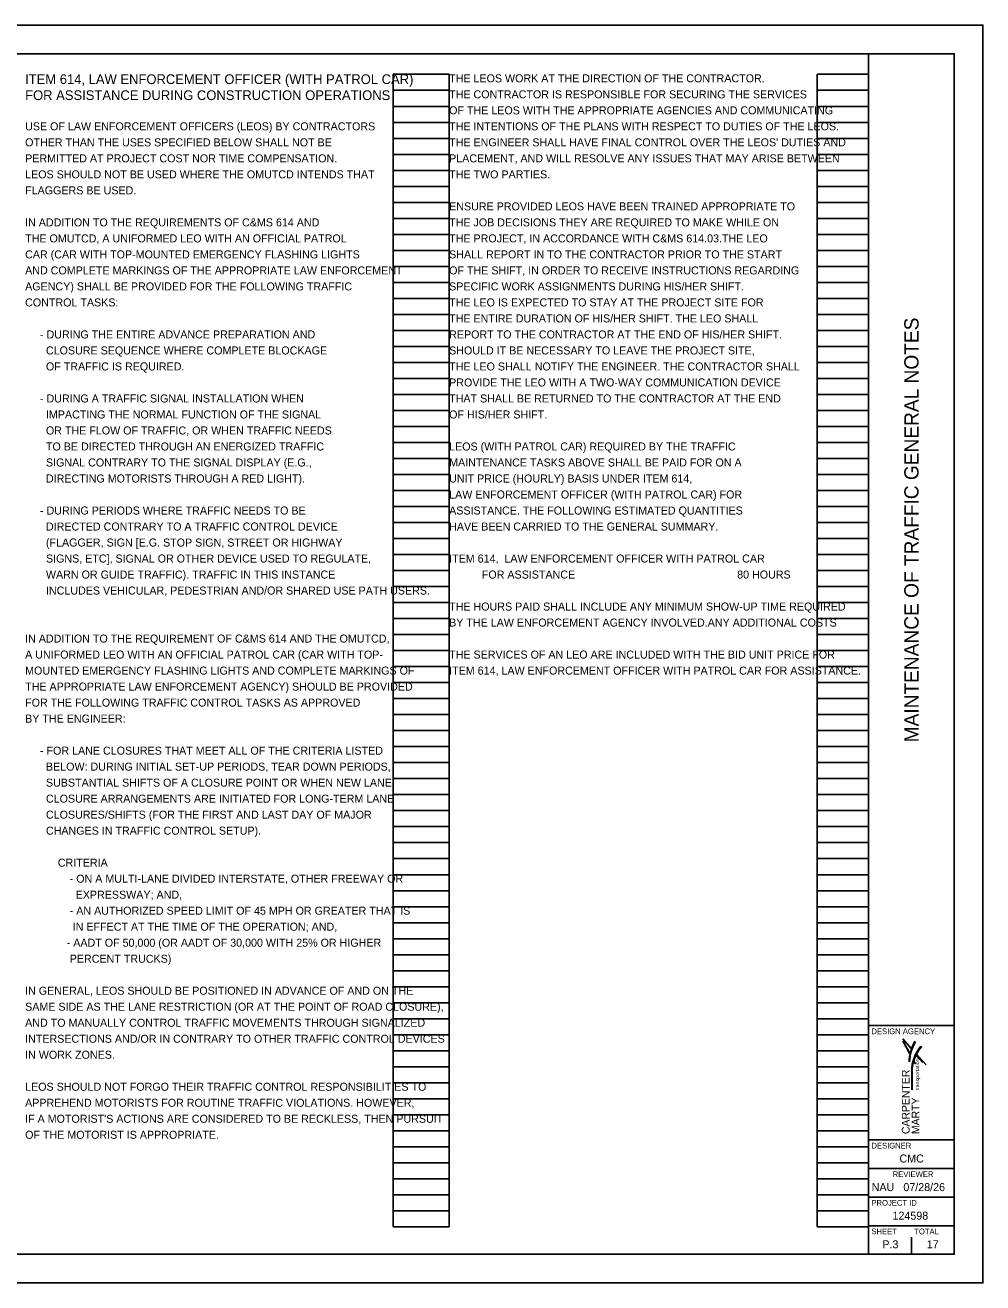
# Model space of a CAD drawing. Extents: x 0 to 34, y -31.6 to -9.6.
# Drawn here: x 17.24 to 34, y -31.62 to -9.62 of the extents above; entities that cross this region are included whole.
import ezdxf

# ---------------------------------------------------------------- set-up
doc = ezdxf.new("R2010")
doc.units = 0
for name, color, linetype in [('SH_Border', 7, 'Continuous'), ('SH_Cut_Line', 7, 'Continuous'), ('SH_Data', 7, 'Continuous'), ('SH_Text', 7, 'Continuous')]:
    doc.layers.add(name, color=color, linetype=linetype)

msp = doc.modelspace()

# ---------------------------------------------------------------- linework, layer by layer
at = {"layer": 'SH_Border'}
for p, q in [((32, -31.117), (32, -10.117)), ((32, -27.117), (33.5, -27.117)), ((32, -29.117), (33.5, -29.117)), ((32, -29.617), (33.5, -29.617)), ((32, -30.117), (33.5, -30.117)), ((32, -30.617), (33.5, -30.617))]:
    msp.add_line(p, q, dxfattribs=at)
msp.add_lwpolyline([(1.5, -10.117), (33.5, -10.117), (33.5, -31.117), (1.5, -31.117)], close=True, dxfattribs=at)
at = {"layer": 'SH_Cut_Line'}
msp.add_lwpolyline([(0, -31.617), (34, -31.617), (34, -9.617), (0, -9.617)], close=True, dxfattribs=at)
at = {"layer": 'SH_Data'}
for p, q in [((23.68, -30.637), (23.68, -10.477)), ((23.68, -10.477), (24.66, -10.477)), ((24.66, -30.637), (24.66, -10.477)), ((31.1, -30.637), (31.1, -10.477)), ((31.1, -10.477), (32, -10.477)), ((32, -30.637), (32, -10.477)), ((23.68, -10.757), (24.66, -10.757)), ((31.1, -10.757), (32, -10.757)), ((23.68, -11.037), (24.66, -11.037)), ((31.1, -11.037), (32, -11.037)), ((23.68, -11.317), (24.66, -11.317)), ((31.1, -11.317), (32, -11.317)), ((23.68, -11.597), (24.66, -11.597)), ((31.1, -11.597), (32, -11.597)), ((23.68, -11.877), (24.66, -11.877)), ((31.1, -11.877), (32, -11.877)), ((23.68, -12.157), (24.66, -12.157)), ((31.1, -12.157), (32, -12.157)), ((23.68, -12.437), (24.66, -12.437)), ((31.1, -12.437), (32, -12.437)), ((23.68, -12.717), (24.66, -12.717)), ((31.1, -12.717), (32, -12.717)), ((23.68, -12.997), (24.66, -12.997)), ((31.1, -12.997), (32, -12.997)), ((23.68, -13.277), (24.66, -13.277)), ((31.1, -13.277), (32, -13.277)), ((23.68, -13.557), (24.66, -13.557)), ((31.1, -13.557), (32, -13.557)), ((23.68, -13.837), (24.66, -13.837)), ((31.1, -13.837), (32, -13.837)), ((23.68, -14.117), (24.66, -14.117)), ((31.1, -14.117), (32, -14.117)), ((23.68, -14.397), (24.66, -14.397)), ((31.1, -14.397), (32, -14.397)), ((23.68, -14.677), (24.66, -14.677)), ((31.1, -14.677), (32, -14.677)), ((23.68, -14.957), (24.66, -14.957)), ((31.1, -14.957), (32, -14.957)), ((23.68, -15.237), (24.66, -15.237)), ((31.1, -15.237), (32, -15.237)), ((23.68, -15.517), (24.66, -15.517)), ((31.1, -15.517), (32, -15.517)), ((23.68, -15.797), (24.66, -15.797)), ((31.1, -15.797), (32, -15.797)), ((23.68, -16.077), (24.66, -16.077)), ((31.1, -16.077), (32, -16.077)), ((23.68, -16.357), (24.66, -16.357)), ((31.1, -16.357), (32, -16.357)), ((23.68, -16.637), (24.66, -16.637)), ((31.1, -16.637), (32, -16.637)), ((23.68, -16.917), (24.66, -16.917)), ((31.1, -16.917), (32, -16.917)), ((23.68, -17.197), (24.66, -17.197)), ((31.1, -17.197), (32, -17.197)), ((23.68, -17.477), (24.66, -17.477)), ((31.1, -17.477), (32, -17.477)), ((23.68, -17.757), (24.66, -17.757)), ((31.1, -17.757), (32, -17.757)), ((23.68, -18.037), (24.66, -18.037)), ((31.1, -18.037), (32, -18.037)), ((23.68, -18.317), (24.66, -18.317)), ((31.1, -18.317), (32, -18.317)), ((23.68, -18.597), (24.66, -18.597)), ((31.1, -18.597), (32, -18.597)), ((23.68, -18.877), (24.66, -18.877)), ((31.1, -18.877), (32, -18.877)), ((23.68, -19.157), (24.66, -19.157)), ((31.1, -19.157), (32, -19.157)), ((23.68, -19.437), (24.66, -19.437)), ((31.1, -19.437), (32, -19.437)), ((23.68, -19.717), (24.66, -19.717)), ((31.1, -19.717), (32, -19.717)), ((23.68, -19.997), (24.66, -19.997)), ((31.1, -19.997), (32, -19.997)), ((23.68, -20.277), (24.66, -20.277)), ((31.1, -20.277), (32, -20.277)), ((23.68, -20.557), (24.66, -20.557)), ((31.1, -20.557), (32, -20.557)), ((23.68, -20.837), (24.66, -20.837)), ((31.1, -20.837), (32, -20.837)), ((23.68, -21.117), (24.66, -21.117)), ((31.1, -21.117), (32, -21.117)), ((23.68, -21.397), (24.66, -21.397)), ((31.1, -21.397), (32, -21.397)), ((23.68, -21.677), (24.66, -21.677)), ((31.1, -21.677), (32, -21.677)), ((23.68, -21.957), (24.66, -21.957)), ((31.1, -21.957), (32, -21.957)), ((23.68, -22.237), (24.66, -22.237)), ((31.1, -22.237), (32, -22.237)), ((23.68, -22.517), (24.66, -22.517)), ((31.1, -22.517), (32, -22.517)), ((23.68, -22.797), (24.66, -22.797)), ((31.1, -22.797), (32, -22.797)), ((23.68, -23.077), (24.66, -23.077)), ((31.1, -23.077), (32, -23.077)), ((23.68, -23.357), (24.66, -23.357)), ((31.1, -23.357), (32, -23.357)), ((23.68, -23.637), (24.66, -23.637)), ((31.1, -23.637), (32, -23.637)), ((23.68, -23.917), (24.66, -23.917)), ((31.1, -23.917), (32, -23.917)), ((23.68, -24.197), (24.66, -24.197)), ((31.1, -24.197), (32, -24.197)), ((23.68, -24.477), (24.66, -24.477)), ((31.1, -24.477), (32, -24.477)), ((23.68, -24.757), (24.66, -24.757)), ((31.1, -24.757), (32, -24.757)), ((23.68, -25.037), (24.66, -25.037)), ((31.1, -25.037), (32, -25.037)), ((23.68, -25.317), (24.66, -25.317)), ((31.1, -25.317), (32, -25.317)), ((23.68, -25.597), (24.66, -25.597)), ((31.1, -25.597), (32, -25.597)), ((23.68, -25.877), (24.66, -25.877)), ((31.1, -25.877), (32, -25.877)), ((23.68, -26.157), (24.66, -26.157)), ((31.1, -26.157), (32, -26.157)), ((23.68, -26.437), (24.66, -26.437)), ((31.1, -26.437), (32, -26.437)), ((23.68, -26.717), (24.66, -26.717)), ((31.1, -26.717), (32, -26.717)), ((23.68, -26.997), (24.66, -26.997)), ((31.1, -26.997), (32, -26.997)), ((23.68, -27.277), (24.66, -27.277)), ((31.1, -27.277), (32, -27.277)), ((23.68, -27.557), (24.66, -27.557)), ((31.1, -27.557), (32, -27.557)), ((23.68, -27.837), (24.66, -27.837)), ((31.1, -27.837), (32, -27.837)), ((23.68, -28.117), (24.66, -28.117)), ((31.1, -28.117), (32, -28.117)), ((32.75, -28.117), (32.75, -28.117)), ((23.68, -28.397), (24.66, -28.397)), ((31.1, -28.397), (32, -28.397)), ((23.68, -28.677), (24.66, -28.677)), ((31.1, -28.677), (32, -28.677)), ((23.68, -28.957), (24.66, -28.957)), ((31.1, -28.957), (32, -28.957)), ((23.68, -29.237), (24.66, -29.237)), ((31.1, -29.237), (32, -29.237)), ((23.68, -29.517), (24.66, -29.517)), ((31.1, -29.517), (32, -29.517)), ((23.68, -29.797), (24.66, -29.797)), ((31.1, -29.797), (32, -29.797)), ((23.68, -30.077), (24.66, -30.077)), ((31.1, -30.077), (32, -30.077)), ((23.68, -30.357), (24.66, -30.357)), ((31.1, -30.357), (32, -30.357)), ((23.68, -30.637), (24.66, -30.637)), ((31.1, -30.637), (32, -30.637)), ((32.375, -30.942), (32.375, -30.942)), ((32.75, -31.117), (32.75, -30.817))]:
    msp.add_line(p, q, dxfattribs=at)
at = {"layer": 'SH_Text'}
for p, q in [((32.721, -27.6), (32.602, -27.385)), ((32.952, -27.764), (32.834, -27.626)), ((32.839, -27.615), (33.006, -27.801)), ((32.755, -28.239), (32.755, -27.913)), ((32.762, -28.239), (32.762, -27.913)), ((32.811, -27.776), (32.79, -27.737)), ((32.82, -27.783), (32.791, -27.731))]:
    msp.add_line(p, q, dxfattribs=at)
for points in [[(32.746, -27.513), (32.601, -27.351)], [(32.601, -27.351), (32.744, -27.519)], [(32.721, -27.6), (32.602, -27.385)], [(32.602, -27.385), (32.719, -27.606)]]:
    msp.add_lwpolyline(points, dxfattribs=at)
for centre, radius, start, end in [((33.432, -27.757), 0.721, 149.5704, 179.5529), ((33.373, -27.755), 0.654, 147.1423, 179.6525), ((33.426, -27.913), 0.671, 139.2898, 180.0106), ((33.433, -27.929), 0.672, 138.5126, 178.6075)]:
    msp.add_arc(centre, radius, start, end, dxfattribs=at)

# ---------------------------------------------------------------- texts
at = {"layer": 'SH_Data'}
msp.add_text('MAINTENANCE OF TRAFFIC GENERAL NOTES', height=0.25, rotation=90, dxfattribs=at).set_placement((32.875, -22.162))
for s, height, p in [('DESIGN AGENCY', 0.1, (32.05, -27.267)), ('DESIGNER', 0.1, (32.05, -29.267)), ('CMC', 0.14, (32.541, -29.512)), ('REVIEWER', 0.1, (32.422, -29.767)), ('NAU', 0.14, (32.055, -30.012)), ('07/28/26', 0.14, (32.609, -30.012)), ('PROJECT ID', 0.1, (32.05, -30.267)), ('124598', 0.14, (32.419, -30.512)), ('SHEET', 0.1, (32.05, -30.767)), ('TOTAL', 0.1, (32.8, -30.767)), ('P.3', 0.14, (32.241, -31.012)), ('17', 0.14, (33.018, -31.012))]:
    msp.add_text(s, height=height, dxfattribs=at).set_placement(p)
at = {"layer": 'SH_Text'}
for s, height, p in [('ITEM 614, LAW ENFORCEMENT OFFICER (WITH PATROL CAR)', 0.17, (17.24, -10.647)), ('THE LEOS WORK AT THE DIRECTION OF THE CONTRACTOR.', 0.14, (24.66, -10.617)), ('FOR ASSISTANCE DURING CONSTRUCTION OPERATIONS', 0.17, (17.24, -10.927)), ('THE CONTRACTOR IS RESPONSIBLE FOR SECURING THE SERVICES', 0.14, (24.66, -10.897)), ('OF THE LEOS WITH THE APPROPRIATE AGENCIES AND COMMUNICATING', 0.14, (24.66, -11.177)), ('USE OF LAW ENFORCEMENT OFFICERS (LEOS) BY CONTRACTORS', 0.14, (17.24, -11.457)), ('THE INTENTIONS OF THE PLANS WITH RESPECT TO DUTIES OF THE LEOS.', 0.14, (24.66, -11.457)), ('OTHER THAN THE USES SPECIFIED BELOW SHALL NOT BE', 0.14, (17.24, -11.737)), ("THE ENGINEER SHALL HAVE FINAL CONTROL OVER THE LEOS' DUTIES AND", 0.14, (24.66, -11.737)), ('PERMITTED AT PROJECT COST NOR TIME COMPENSATION.', 0.14, (17.24, -12.017)), ('PLACEMENT, AND WILL RESOLVE ANY ISSUES THAT MAY ARISE BETWEEN', 0.14, (24.66, -12.017)), ('LEOS SHOULD NOT BE USED WHERE THE OMUTCD INTENDS THAT', 0.14, (17.24, -12.297)), ('THE TWO PARTIES.', 0.14, (24.66, -12.297)), ('FLAGGERS BE USED.', 0.14, (17.24, -12.577)), ('ENSURE PROVIDED LEOS HAVE BEEN TRAINED APPROPRIATE TO', 0.14, (24.66, -12.857)), ('IN ADDITION TO THE REQUIREMENTS OF C&MS 614 AND', 0.14, (17.24, -13.137)), ('THE JOB DECISIONS THEY ARE REQUIRED TO MAKE WHILE ON', 0.14, (24.66, -13.137)), ('THE OMUTCD, A UNIFORMED LEO WITH AN OFFICIAL PATROL', 0.14, (17.24, -13.417)), ('THE PROJECT, IN ACCORDANCE WITH C&MS 614.03.THE LEO', 0.14, (24.66, -13.417)), ('CAR (CAR WITH TOP-MOUNTED EMERGENCY FLASHING LIGHTS', 0.14, (17.24, -13.697)), ('SHALL REPORT IN TO THE CONTRACTOR PRIOR TO THE START', 0.14, (24.66, -13.697)), ('AND COMPLETE MARKINGS OF THE APPROPRIATE LAW ENFORCEMENT', 0.14, (17.24, -13.977)), ('OF THE SHIFT, IN ORDER TO RECEIVE INSTRUCTIONS REGARDING', 0.14, (24.66, -13.977)), ('AGENCY) SHALL BE PROVIDED FOR THE FOLLOWING TRAFFIC', 0.14, (17.24, -14.257)), ('SPECIFIC WORK ASSIGNMENTS DURING HIS/HER SHIFT.', 0.14, (24.66, -14.257)), ('CONTROL TASKS:', 0.14, (17.24, -14.537)), ('THE LEO IS EXPECTED TO STAY AT THE PROJECT SITE FOR', 0.14, (24.66, -14.537)), ('THE ENTIRE DURATION OF HIS/HER SHIFT. THE LEO SHALL', 0.14, (24.66, -14.817)), ('     - DURING THE ENTIRE ADVANCE PREPARATION AND', 0.14, (17.24, -15.097)), ('REPORT TO THE CONTRACTOR AT THE END OF HIS/HER SHIFT.', 0.14, (24.66, -15.097)), ('       CLOSURE SEQUENCE WHERE COMPLETE BLOCKAGE', 0.14, (17.24, -15.377)), ('SHOULD IT BE NECESSARY TO LEAVE THE PROJECT SITE,', 0.14, (24.66, -15.377)), ('       OF TRAFFIC IS REQUIRED.', 0.14, (17.24, -15.657)), ('THE LEO SHALL NOTIFY THE ENGINEER. THE CONTRACTOR SHALL', 0.14, (24.66, -15.657)), ('PROVIDE THE LEO WITH A TWO-WAY COMMUNICATION DEVICE', 0.14, (24.66, -15.937)), ('     - DURING A TRAFFIC SIGNAL INSTALLATION WHEN', 0.14, (17.24, -16.217)), ('THAT SHALL BE RETURNED TO THE CONTRACTOR AT THE END', 0.14, (24.66, -16.217)), ('       IMPACTING THE NORMAL FUNCTION OF THE SIGNAL', 0.14, (17.24, -16.497)), ('OF HIS/HER SHIFT.', 0.14, (24.66, -16.497)), ('       OR THE FLOW OF TRAFFIC, OR WHEN TRAFFIC NEEDS', 0.14, (17.24, -16.777)), ('       TO BE DIRECTED THROUGH AN ENERGIZED TRAFFIC', 0.14, (17.24, -17.057)), ('LEOS (WITH PATROL CAR) REQUIRED BY THE TRAFFIC', 0.14, (24.66, -17.057)), ('       SIGNAL CONTRARY TO THE SIGNAL DISPLAY (E.G.,', 0.14, (17.24, -17.337)), ('MAINTENANCE TASKS ABOVE SHALL BE PAID FOR ON A', 0.14, (24.66, -17.337)), ('       DIRECTING MOTORISTS THROUGH A RED LIGHT).', 0.14, (17.24, -17.617)), ('UNIT PRICE (HOURLY) BASIS UNDER ITEM 614,', 0.14, (24.66, -17.617)), ('LAW ENFORCEMENT OFFICER (WITH PATROL CAR) FOR', 0.14, (24.66, -17.897)), ('     - DURING PERIODS WHERE TRAFFIC NEEDS TO BE', 0.14, (17.24, -18.177)), ('ASSISTANCE. THE FOLLOWING ESTIMATED QUANTITIES', 0.14, (24.66, -18.177)), ('       DIRECTED CONTRARY TO A TRAFFIC CONTROL DEVICE', 0.14, (17.24, -18.457)), ('HAVE BEEN CARRIED TO THE GENERAL SUMMARY.', 0.14, (24.66, -18.457)), ('       (FLAGGER, SIGN [E.G. STOP SIGN, STREET OR HIGHWAY', 0.14, (17.24, -18.737)), ('       SIGNS, ETC], SIGNAL OR OTHER DEVICE USED TO REGULATE,', 0.14, (17.24, -19.017)), ('ITEM 614,  LAW ENFORCEMENT OFFICER WITH PATROL CAR', 0.14, (24.66, -19.017)), ('       WARN OR GUIDE TRAFFIC). TRAFFIC IN THIS INSTANCE', 0.14, (17.24, -19.297)), ('           FOR ASSISTANCE ', 0.14, (24.66, -19.297)), ('80 HOURS', 0.14, (29.7, -19.297)), ('       INCLUDES VEHICULAR, PEDESTRIAN AND/OR SHARED USE PATH USERS.', 0.14, (17.24, -19.577)), ('THE HOURS PAID SHALL INCLUDE ANY MINIMUM SHOW-UP TIME REQUIRED', 0.14, (24.66, -19.857)), ('BY THE LAW ENFORCEMENT AGENCY INVOLVED.ANY ADDITIONAL COSTS', 0.14, (24.66, -20.137)), ('IN ADDITION TO THE REQUIREMENT OF C&MS 614 AND THE OMUTCD,', 0.14, (17.24, -20.417)), ('A UNIFORMED LEO WITH AN OFFICIAL PATROL CAR (CAR WITH TOP-', 0.14, (17.24, -20.697)), ('THE SERVICES OF AN LEO ARE INCLUDED WITH THE BID UNIT PRICE FOR', 0.14, (24.66, -20.697)), ('MOUNTED EMERGENCY FLASHING LIGHTS AND COMPLETE MARKINGS OF', 0.14, (17.24, -20.977)), ('ITEM 614, LAW ENFORCEMENT OFFICER WITH PATROL CAR FOR ASSISTANCE.', 0.14, (24.66, -20.977)), ('THE APPROPRIATE LAW ENFORCEMENT AGENCY) SHOULD BE PROVIDED', 0.14, (17.24, -21.257)), ('FOR THE FOLLOWING TRAFFIC CONTROL TASKS AS APPROVED', 0.14, (17.24, -21.537)), ('BY THE ENGINEER:', 0.14, (17.24, -21.817)), ('     - FOR LANE CLOSURES THAT MEET ALL OF THE CRITERIA LISTED', 0.14, (17.24, -22.377)), ('       BELOW: DURING INITIAL SET-UP PERIODS, TEAR DOWN PERIODS,', 0.14, (17.24, -22.657)), ('       SUBSTANTIAL SHIFTS OF A CLOSURE POINT OR WHEN NEW LANE', 0.14, (17.24, -22.937)), ('       CLOSURE ARRANGEMENTS ARE INITIATED FOR LONG-TERM LANE', 0.14, (17.24, -23.217)), ('       CLOSURES/SHIFTS (FOR THE FIRST AND LAST DAY OF MAJOR', 0.14, (17.24, -23.497)), ('       CHANGES IN TRAFFIC CONTROL SETUP).', 0.14, (17.24, -23.777)), ('           CRITERIA', 0.14, (17.24, -24.337)), ('               - ON A MULTI-LANE DIVIDED INTERSTATE, OTHER FREEWAY OR', 0.14, (17.24, -24.617)), ('                 EXPRESSWAY; AND,', 0.14, (17.24, -24.897)), ('               - AN AUTHORIZED SPEED LIMIT OF 45 MPH OR GREATER THAT IS', 0.14, (17.24, -25.177)), ('                IN EFFECT AT THE TIME OF THE OPERATION; AND,', 0.14, (17.24, -25.457)), ('              - AADT OF 50,000 (OR AADT OF 30,000 WITH 25% OR HIGHER', 0.14, (17.24, -25.737)), ('               PERCENT TRUCKS)', 0.14, (17.24, -26.017)), ('IN GENERAL, LEOS SHOULD BE POSITIONED IN ADVANCE OF AND ON THE', 0.14, (17.24, -26.577)), ('SAME SIDE AS THE LANE RESTRICTION (OR AT THE POINT OF ROAD CLOSURE),', 0.14, (17.24, -26.857)), ('AND TO MANUALLY CONTROL TRAFFIC MOVEMENTS THROUGH SIGNALIZED', 0.14, (17.24, -27.137)), ('INTERSECTIONS AND/OR IN CONTRARY TO OTHER TRAFFIC CONTROL DEVICES', 0.14, (17.24, -27.417)), ('IN WORK ZONES.', 0.14, (17.24, -27.697)), ('LEOS SHOULD NOT FORGO THEIR TRAFFIC CONTROL RESPONSIBILITIES TO', 0.14, (17.24, -28.257)), ('APPREHEND MOTORISTS FOR ROUTINE TRAFFIC VIOLATIONS. HOWEVER,', 0.14, (17.24, -28.537)), ("IF A MOTORIST'S ACTIONS ARE CONSIDERED TO BE RECKLESS, THEN PURSUIT", 0.14, (17.24, -28.817)), ('OF THE MOTORIST IS APPROPRIATE.', 0.14, (17.24, -29.097))]:
    msp.add_text(s, height=height, dxfattribs=at).set_placement(p)
for s, height, p in [('transportation', 0.06649, (32.885, -28.253)), ('CARPENTER ', 0.1367, (32.719, -29.015)), ('MARTY', 0.1367, (32.891, -29.015))]:
    msp.add_text(s, height=height, rotation=90, dxfattribs=at).set_placement(p)

doc.saveas('drawing.dxf')
